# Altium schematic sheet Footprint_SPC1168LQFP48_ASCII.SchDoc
size A4; 项目编号: SPSZ2023-052501A; 项目名称: 三相PFC-2.2KW压机+700W风机
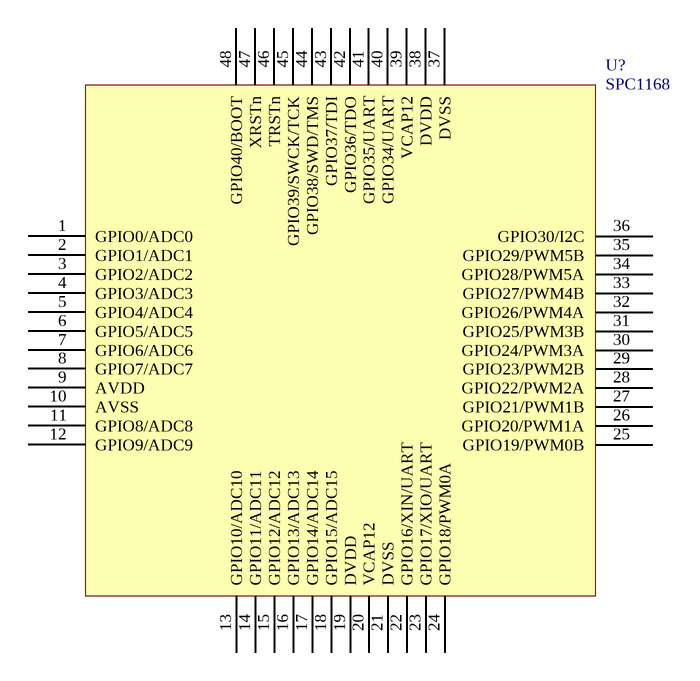
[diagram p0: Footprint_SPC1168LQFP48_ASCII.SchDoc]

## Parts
U?  SPC1168  [PQFP48]

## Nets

Not connected (* = marked no-connect by the designer): U? 1(GPIO0/ADC0) 2(GPIO1/ADC1) 3(GPIO2/ADC2) 4(GPIO3/ADC3) 5(GPIO4/ADC4) 6(GPIO5/ADC5) 7(GPIO6/ADC6) 8(GPIO7/ADC7) 9(AVDD) 10(AVSS) 11(GPIO8/ADC8) 12(GPIO9/ADC9) 13(GPIO10/ADC10) 14(GPIO11/ADC11) 15(GPIO12/ADC12) 16(GPIO13/ADC13) 17(GPIO14/ADC14) 18(GPIO15/ADC15) 19(DVDD) 20(VCAP12) 21(DVSS) 22(GPIO16/XIN/UART) 23(GPIO17/XIO/UART) 24(GPIO18/PWM0A) 25(GPIO19/PWM0B) 26(GPIO20/PWM1A) 27(GPIO21/PWM1B) 28(GPIO22/PWM2A) 29(GPIO23/PWM2B) 30(GPIO24/PWM3A) 31(GPIO25/PWM3B) 32(GPIO26/PWM4A) 33(GPIO27/PWM4B) 34(GPIO28/PWM5A) 35(GPIO29/PWM5B) 36(GPIO30/I2C) 37(DVSS) 38(DVDD) 39(VCAP12) 40(GPIO34/UART) 41(GPIO35/UART) 42(GPIO36/TDO) 43(GPIO37/TDI) 44(GPIO38/SWD/TMS) 45(GPIO39/SWCK/TCK) 46(TRSTn) 47(XRSTn) 48(GPIO40/BOOT)

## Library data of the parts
U? = GECKO: 32-bit ARM CM4 MCU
